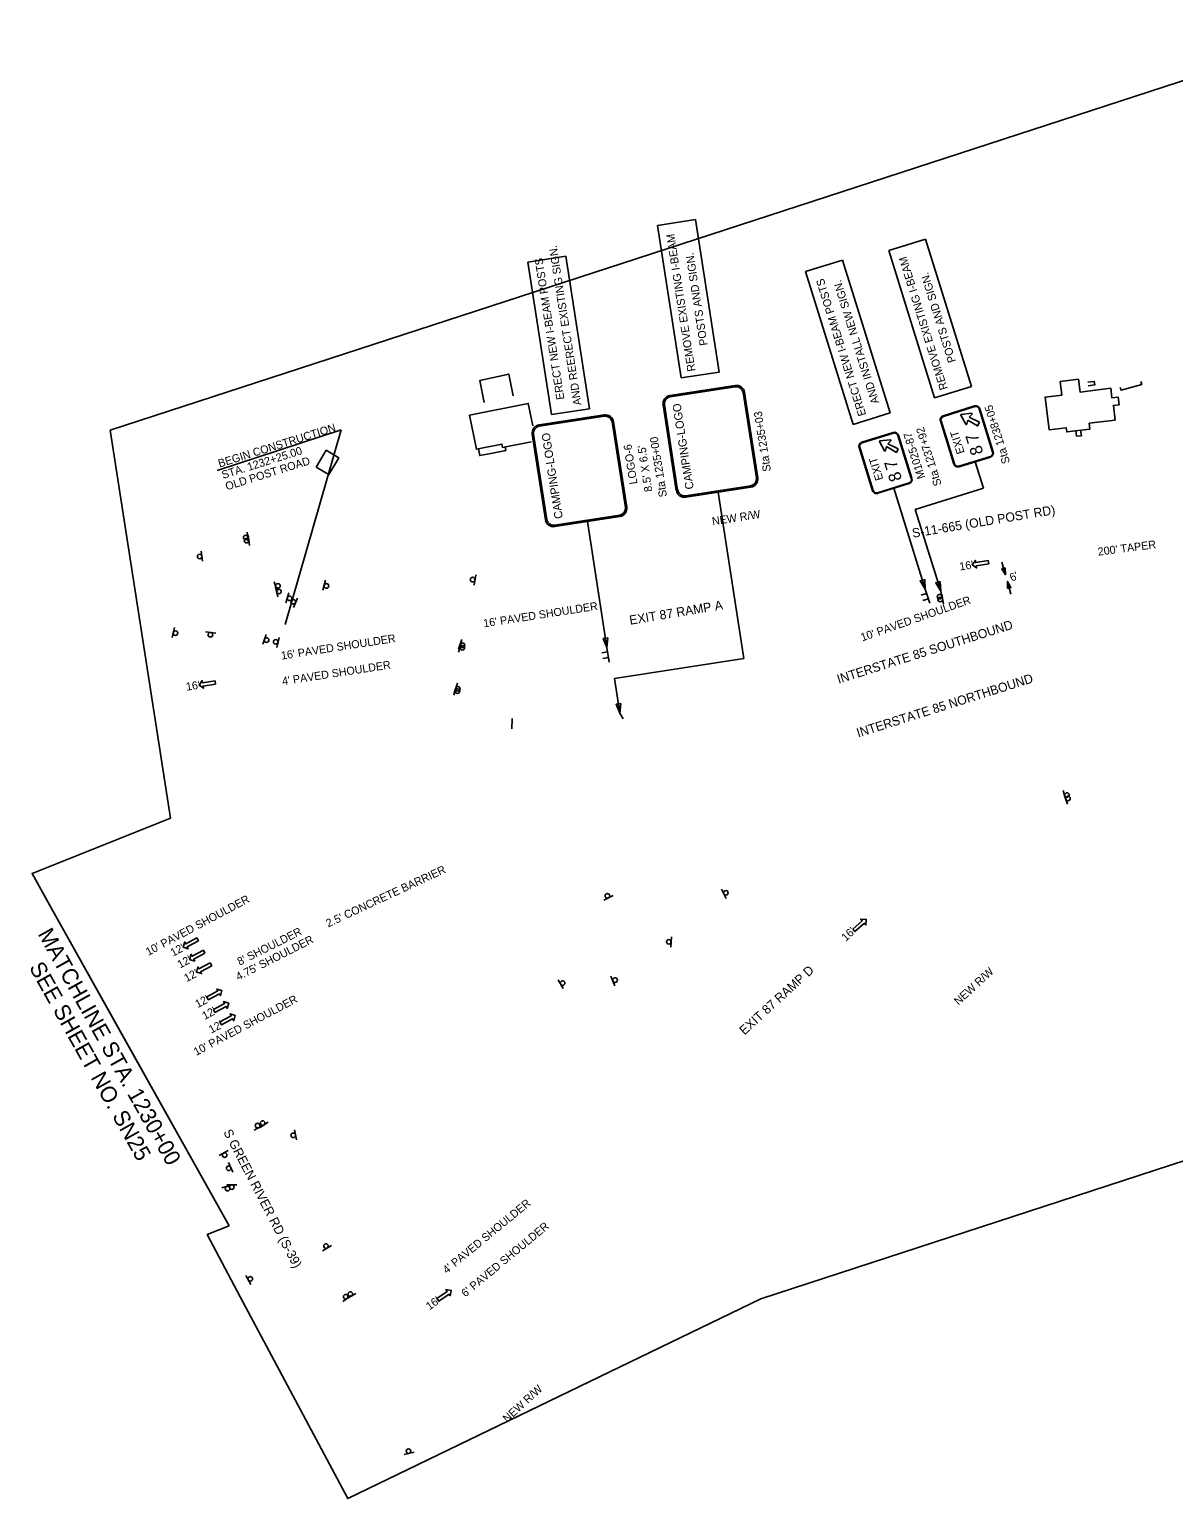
# Model space of a CAD drawing. Extents: x 1772383 to 1773934, y 1178785 to 1180160.
# Drawn here: x 1772383 to 1773384, y 1178785 to 1180070 of the extents above; entities that cross this region are included whole.
import ezdxf

# ---------------------------------------------------------------- set-up
doc = ezdxf.new("R2010")
doc.units = 0
for name, color, linetype in [('RD_EX_Bldg', 7, 'Continuous'), ('RD_EX_Conc', 7, 'Continuous'), ('RD_PD_Final_LnLine', 7, 'Continuous'), ('RD_PD_Final_TX', 7, 'Continuous'), ('RD_PD_RW_TX', 7, 'Continuous'), ('RD_SHT_MatchLine', 7, 'Continuous'), ('RD_SHT_ShtClip', 7, 'Continuous'), ('RD_TX_Drainage', 7, 'Continuous'), ('RD_TX_RoadID', 7, 'Continuous'), ('SN_P_Signs', 7, 'Continuous')]:
    doc.layers.add(name, color=color, linetype=linetype)

# ---------------------------------------------------------------- blocks, each defined once
blk = doc.blocks.new('SARRW2')
at = {"layer": 'RD_PD_Final_LnLine'}
blk.add_lwpolyline([(-12, 1.2), (-12, -1.2), (-2.8, -1.2), (-2.8, -2.8), (0, 0), (-2.8, 2.8), (-2.8, 1.2)], close=True, dxfattribs=at)
blk = doc.blocks.new('AH')
at = {"layer": 'RD_TX_Drainage'}
blk.add_lwpolyline([(-6, 1.5), (0, 0), (-6, -1.5)], close=True, dxfattribs=at)

msp = doc.modelspace()

# ---------------------------------------------------------------- linework, layer by layer
at = {"layer": 'RD_EX_Bldg'}
for points in [[(1773332.8, 1179728.1), (1773310, 1179725.3), (1773310.6, 1179720.2), (1773290.4, 1179717.7), (1773289.9, 1179721.4), (1773275, 1179719.6), (1773271.5, 1179748.1), (1773286.2, 1179749.9), (1773284.7, 1179761.9), (1773300.6, 1179763.8), (1773302, 1179752.6), (1773328.8, 1179755.9), (1773329.9, 1179747.4), (1773335.3, 1179748.1), (1773336.2, 1179741.5), (1773331.2, 1179740.9), (1773332.8, 1179728.1)], [(1772822, 1179709.1), (1772797.1, 1179704.1), (1772796.6, 1179707), (1772774.2, 1179702.5), (1772768.3, 1179732.4), (1772819.6, 1179742.6), (1772823.5, 1179722.9)], [(1772634.2, 1179687), (1772642.9, 1179701.6), (1772653.9, 1179695.1), (1772645.3, 1179680.5), (1772634.2, 1179687)]]:
    msp.add_lwpolyline(points, dxfattribs=at)
at = {"layer": 'RD_EX_Conc'}
msp.add_line((1773299, 1179714), (1773298.4, 1179718.7), dxfattribs=at)
for points in [[(1772781.1, 1179743.5), (1772777.3, 1179762.8), (1772802.5, 1179768.3), (1772806.5, 1179749.2)], [(1773309.2, 1179758), (1773314.9, 1179758.8), (1773314.5, 1179761.9), (1773308.9, 1179761.2)], [(1773337, 1179756.6), (1773337.9, 1179754.1), (1773356, 1179759.3), (1773355.2, 1179761.8)], [(1773302.3, 1179719.2), (1773303.2, 1179714.4), (1773299, 1179714)], [(1772776.1, 1179702.9), (1772777.2, 1179697), (1772786.9, 1179698.9), (1772800.1, 1179701.5), (1772799.5, 1179704.6)]]:
    msp.add_lwpolyline(points, dxfattribs=at)
at = {"layer": 'RD_PD_Final_TX'}
for p, q in [((1772547.5, 1179684), (1772656.1, 1179719.4)), ((1772606.9, 1179549.3), (1772656.1, 1179719.4)), ((1773236.9, 1179592.7), (1773233.6, 1179603.7)), ((1773238.5, 1179586.9), (1773241.6, 1179575.9))]:
    msp.add_line(p, q, dxfattribs=at)
at = {"layer": 'RD_SHT_MatchLine'}
msp.add_lwpolyline([(1772545.9, 1179045.1), (1772463.5, 1179192.4), (1772402.4, 1179301.5)], dxfattribs=at)
at = {"layer": 'RD_SHT_ShtClip'}
msp.add_lwpolyline([(1772558.1, 1179023.3), (1772538.9, 1179015.6), (1772567.8, 1178961.2), (1772661.7, 1178784.6), (1773022.9, 1178959.4), (1773601.8, 1179148.2), (1773904.9, 1179498.8), (1773856.3, 1179813.1), (1773835, 1179950.4), (1773829.6, 1179985.5), (1773529.5, 1180069.8), (1772454.1, 1179719.2), (1772506.7, 1179379.7), (1772385.8, 1179331.3), (1772402.4, 1179301.5), (1772545.9, 1179045.1)], close=True, dxfattribs=at)
at = {"layer": 'SN_P_Signs'}
for p, q in [((1772932.6, 1179898.3), (1772965.8, 1179903.4)), ((1772953.2, 1179764.9), (1772932.6, 1179898.3)), ((1772965.8, 1179903.4), (1772986.5, 1179770)), ((1773134.7, 1179876.4), (1773166.8, 1179886.4)), ((1773166.8, 1179886.4), (1773207, 1179757.5)), ((1772819.1, 1179866.3), (1772852.3, 1179871.4)), ((1772852.3, 1179871.4), (1772873, 1179738)), ((1773062.1, 1179858), (1773094.2, 1179868)), ((1773094.2, 1179868), (1773135.9, 1179734.3)), ((1773174.9, 1179747.5), (1773134.7, 1179876.4)), ((1772839.8, 1179732.9), (1772819.1, 1179866.3)), ((1773103.8, 1179724.3), (1773062.1, 1179858)), ((1772986.5, 1179770), (1772953.2, 1179764.9)), ((1773207, 1179757.5), (1773174.9, 1179747.5)), ((1773182.3, 1179731.8), (1773209.8, 1179740.4)), ((1773182.5, 1179731.3), (1773210, 1179739.8)), ((1772873, 1179738), (1772839.8, 1179732.9)), ((1773135.9, 1179734.3), (1773103.8, 1179724.3)), ((1773191.7, 1179689.5), (1773179.9, 1179727.3)), ((1773192.3, 1179689.7), (1773180.5, 1179727.5)), ((1773213.7, 1179737.9), (1773225.5, 1179700.1)), ((1773214.3, 1179738), (1773226.1, 1179700.2)), ((1773111.2, 1179708.7), (1773138.7, 1179717.2)), ((1773111.4, 1179708.1), (1773138.9, 1179716.7)), ((1773142.6, 1179714.7), (1773154.4, 1179676.9)), ((1773143.2, 1179714.9), (1773155, 1179677.1)), ((1773120.6, 1179666.3), (1773108.8, 1179704.1)), ((1773121.2, 1179666.5), (1773109.4, 1179704.3)), ((1773223.6, 1179696.3), (1773196.1, 1179687.7)), ((1773223.7, 1179695.7), (1773196.2, 1179687.2)), ((1773210.3, 1179691.5), (1773217.5, 1179668.5)), ((1772985.7, 1179665), (1773008.2, 1179519.4)), ((1773152.5, 1179673.1), (1773125, 1179664.5)), ((1773152.6, 1179672.6), (1773125.1, 1179664)), ((1773139.2, 1179668.4), (1773166.7, 1179580.2)), ((1773158, 1179649.9), (1773217.5, 1179668.5)), ((1773158, 1179649.9), (1773180.3, 1179578.3)), ((1772871.3, 1179639.3), (1772888.3, 1179529.1)), ((1772575.1, 1179621.1), (1772573.9, 1179630)), ((1772575.8, 1179618.4), (1772574.6, 1179627.3)), ((1772534.9, 1179604.5), (1772533.7, 1179613.4)), ((1772597.3, 1179586.7), (1772600.2, 1179578.2)), ((1772642.4, 1179588), (1772639.9, 1179579.3)), ((1772772.2, 1179583.7), (1772773.6, 1179592.6)), ((1772598.5, 1179582), (1772600.7, 1179573.3)), ((1772610.2, 1179577), (1772607.7, 1179568.3)), ((1772614.2, 1179564.1), (1772617.7, 1179572.4)), ((1773167.9, 1179576.5), (1773163.1, 1179575)), ((1773169.4, 1179571.7), (1773164.6, 1179570.2)), ((1773166.7, 1179580.2), (1773170.6, 1179567.8)), ((1773182.1, 1179569.5), (1773180.3, 1179578.3)), ((1773182.5, 1179567), (1773181.1, 1179575.9)), ((1772510.2, 1179546.6), (1772508.3, 1179537.8)), ((1772546.4, 1179541.8), (1772537.5, 1179542.9)), ((1772590.5, 1179540.5), (1772587.4, 1179532)), ((1772599.7, 1179529.2), (1772601.7, 1179538)), ((1772761.5, 1179536.1), (1772758.6, 1179527.6)), ((1772761.3, 1179533.7), (1772758.7, 1179525.1)), ((1772888.9, 1179525.3), (1772884, 1179524.5)), ((1772889.7, 1179520.3), (1772884.8, 1179519.5)), ((1772888.3, 1179529.1), (1772890.3, 1179516.2)), ((1773008.2, 1179519.4), (1772895, 1179501.9)), ((1772757.3, 1179495.8), (1772754.4, 1179487.3)), ((1772757.6, 1179497.9), (1772754.7, 1179489.4)), ((1772895, 1179501.9), (1772899.7, 1179471.7)), ((1772902.5, 1179466.7), (1772899.7, 1179471.7)), ((1772805.2, 1179458), (1772805.6, 1179467)), ((1773287.4, 1179403.9), (1773290, 1179395.3)), ((1773288, 1179400.6), (1773291.1, 1179392.2)), ((1772988.5, 1179317.7), (1772992.5, 1179309.6)), ((1772885.8, 1179308), (1772893.7, 1179312.2)), ((1772944.2, 1179267), (1772944.8, 1179276)), ((1772845.8, 1179238.5), (1772850.2, 1179230.7)), ((1772891.9, 1179241.6), (1772895.4, 1179233.3)), ((1772579.9, 1179107), (1772587.9, 1179111.2)), ((1772584.7, 1179109), (1772592.3, 1179113.8)), ((1772617, 1179098.5), (1772615.1, 1179107.2)), ((1772557.1, 1179089), (1772549.2, 1179084.8)), ((1772561.2, 1179070.3), (1772557.6, 1179078.6)), ((1772560.5, 1179059.1), (1772551.8, 1179056.5)), ((1772564.9, 1179059.1), (1772555.9, 1179059.1)), ((1772639.7, 1179001.5), (1772647.6, 1179005.9)), ((1772572.6, 1178979.9), (1772576.9, 1178972)), ((1772657.4, 1178956.9), (1772664.7, 1178962.3)), ((1772661.1, 1178959.6), (1772668.9, 1178964.1)), ((1772711, 1178823.1), (1772719.8, 1178825.1))]:
    msp.add_line(p, q, dxfattribs=at)
for points in [[(1772943.5, 1179749.5), (1773000.4, 1179758.3)], [(1772943.7, 1179748.3), (1773000.6, 1179757.2)], [(1773007.4, 1179752.1), (1773019, 1179677.4)], [(1773008.6, 1179752.3), (1773020.2, 1179677.6)], [(1772949, 1179666.6), (1772937.5, 1179741.3)], [(1772950.2, 1179666.8), (1772938.7, 1179741.5)], [(1772829.1, 1179723.8), (1772886, 1179732.6)], [(1772829.2, 1179722.6), (1772886.2, 1179731.4)], [(1772893, 1179726.4), (1772904.6, 1179651.7)], [(1772894.2, 1179726.6), (1772905.8, 1179651.9)], [(1773202.2, 1179724.4), (1773197.8, 1179732.4)], [(1773198.2, 1179733), (1773207.2, 1179734)], [(1773203.9, 1179728.1), (1773203, 1179724.5)], [(1773214.2, 1179726.2), (1773212.5, 1179723), (1773203.9, 1179728.1)], [(1773207.6, 1179733.2), (1773205.1, 1179730.5)], [(1773205.1, 1179730.5), (1773214.2, 1179726.2)], [(1772834.6, 1179640.9), (1772823, 1179715.6)], [(1772835.8, 1179641.1), (1772824.2, 1179715.8)], [(1773131.1, 1179701.2), (1773126.8, 1179709.2)], [(1773127.1, 1179709.8), (1773136.1, 1179710.8)], [(1773132.8, 1179704.9), (1773131.9, 1179701.3)], [(1773143.1, 1179703), (1773141.5, 1179699.8), (1773132.8, 1179704.9)], [(1773136.5, 1179710), (1773134, 1179707.3)], [(1773134, 1179707.3), (1773143.1, 1179703)], [(1773014, 1179670.6), (1772957.1, 1179661.8)], [(1773014.2, 1179669.4), (1772957.3, 1179660.6)], [(1772899.6, 1179644.9), (1772842.6, 1179636)], [(1772899.7, 1179643.7), (1772842.8, 1179634.9)]]:
    msp.add_lwpolyline(points, dxfattribs=at)
for points in [[(1773166.2, 1179588.7), (1773166.7, 1179580.2), (1773162.3, 1179587.5)], [(1773179.8, 1179586.8), (1773180.3, 1179578.3), (1773175.9, 1179585.6)], [(1772889.1, 1179537.5), (1772888.3, 1179529.1), (1772885.1, 1179536.9)], [(1772900.4, 1179480.2), (1772899.7, 1179471.7), (1772896.4, 1179479.5)]]:
    msp.add_lwpolyline(points, close=True, dxfattribs=at)
for centre in [(1772572.5, 1179625.3), (1772573.2, 1179622.6), (1772532.3, 1179608.7), (1772600.7, 1179583.1), (1772643.1, 1179583), (1772770.9, 1179588.5), (1772601.6, 1179578.1), (1772610.9, 1179572.1), (1773179.2, 1179573.6), (1773179.8, 1179571.1), (1772614.1, 1179569.1), (1772511.2, 1179541.7), (1772541.7, 1179540.3), (1772590.8, 1179535.6), (1772598.8, 1179534.1), (1772762, 1179531.1), (1772761.9, 1179528.8), (1772758, 1179493), (1772757.7, 1179490.9), (1773290.6, 1179400.1), (1773291.5, 1179397.1), (1772992.3, 1179314.5), (1772888.8, 1179311.9), (1772942.5, 1179271.7), (1772849.7, 1179235.6), (1772895.5, 1179238.2), (1772582.9, 1179110.9), (1772587.4, 1179113.1), (1772614.1, 1179102.4), (1772554.1, 1179085.1), (1772557.6, 1179073.6), (1772556.7, 1179055.8), (1772560.4, 1179057.1), (1772642.7, 1179005.5), (1772576.6, 1178976.9), (1772659.9, 1178961.2), (1772664, 1178963.6), (1772714.9, 1178826.1)]:
    msp.add_circle(centre, 2, dxfattribs=at)
for centre, radius, start, end in [((1773001.5, 1179751.2), 7.2, 8.8, 98.8), ((1773001.5, 1179751.2), 6, 8.8, 98.8), ((1772944.6, 1179742.4), 7.2, 98.8, 188.8), ((1772944.6, 1179742.4), 6, 98.8, 188.8), ((1773210.9, 1179737), 3.6, 17.3283, 107.3283), ((1773210.9, 1179737), 3, 17.3283, 107.3283), ((1772887.1, 1179725.5), 7.2, 8.8, 98.8), ((1772887.1, 1179725.5), 6, 8.8, 98.8), ((1773183.4, 1179728.4), 3.6, 107.3283, 197.3283), ((1773183.4, 1179728.4), 3, 107.3283, 197.3283), ((1773198.2, 1179732.6), 0.45, 96.1504, 208.5062), ((1773207.2, 1179733.5), 0.45, 318.3662, 96.1504), ((1772830.2, 1179716.7), 7.2, 98.8, 188.8), ((1772830.2, 1179716.7), 6, 98.8, 188.8), ((1773139.8, 1179713.8), 3.6, 17.3283, 107.3283), ((1773139.8, 1179713.8), 3, 17.3283, 107.3283), ((1773202.5, 1179724.6), 0.45, 208.5062, 346.2904), ((1773112.3, 1179705.2), 3.6, 107.3283, 197.3283), ((1773112.3, 1179705.2), 3, 107.3283, 197.3283), ((1773127.1, 1179709.4), 0.45, 96.1504, 208.5062), ((1773131.5, 1179701.4), 0.45, 208.5062, 346.2904), ((1773136.1, 1179710.3), 0.45, 318.3662, 96.1504), ((1773222.7, 1179699.2), 3, 287.3283, 17.3283), ((1773222.7, 1179699.2), 3.6, 287.3283, 17.3283), ((1773195.2, 1179690.6), 3.6, 197.3283, 287.3283), ((1773195.2, 1179690.6), 3, 197.3283, 287.3283), ((1773013.1, 1179676.5), 6, 278.8, 8.8), ((1773013.1, 1179676.5), 7.2, 278.8, 8.8), ((1773151.6, 1179676), 3, 287.3283, 17.3283), ((1773151.6, 1179676), 3.6, 287.3283, 17.3283), ((1772956.2, 1179667.7), 7.2, 188.8, 278.8), ((1772956.2, 1179667.7), 6, 188.8, 278.8), ((1773124.1, 1179667.4), 3.6, 197.3283, 287.3283), ((1773124.1, 1179667.4), 3, 197.3283, 287.3283), ((1772898.6, 1179650.8), 6, 278.8, 8.8), ((1772898.6, 1179650.8), 7.2, 278.8, 8.8), ((1772841.7, 1179642), 7.2, 188.8, 278.8), ((1772841.7, 1179642), 6, 188.8, 278.8)]:
    msp.add_arc(centre, radius, start, end, dxfattribs=at)

# ---------------------------------------------------------------- block references
at = {"layer": 'RD_PD_Final_LnLine'}
for p, xscale, yscale, rotation in [((1773207.8, 1179601.5), 1.2, 1.2, -171.19998882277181), ((1772531.7, 1179496.3), 1.2, 1.2, -171.19998882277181), ((1773115.1, 1179291.2), 1.1999999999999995, 1.2000000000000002, 41.435473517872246), ((1773115.1, 1179291.2), 1.1999999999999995, 1.2000000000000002, 41.435473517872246), ((1772517.8, 1179267), 1.2, 1.2000000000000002, -151.9473681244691), ((1772523.5, 1179256.2), 1.2, 1.2000000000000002, -151.9473681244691), ((1772529.4, 1179245.2), 1.2, 1.2000000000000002, -151.9473681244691), ((1772551.8, 1179229), 1.1999999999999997, 1.2000000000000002, 28.052631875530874), ((1772557.7, 1179218), 1.1999999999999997, 1.2000000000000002, 28.052631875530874), ((1772563.4, 1179207.2), 1.1999999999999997, 1.2000000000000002, 28.052631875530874), ((1772752.2, 1178966.7), 1.1999999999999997, 1.1999999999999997, 35.391952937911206)]:
    msp.add_blockref('SARRW2', p, dxfattribs=dict(at, xscale=xscale, yscale=yscale, rotation=rotation))
at = {"layer": 'RD_PD_Final_TX'}
for p, rotation in [((1773236.9, 1179592.7), -73.7125457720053), ((1773238.5, 1179586.9), 105.5366000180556)]:
    msp.add_blockref('AH', p, dxfattribs=dict(at, rotation=rotation))

# ---------------------------------------------------------------- texts
for s, rotation, p in [('BEGIN CONSTRUCTION', 17.4349, (1772549.7, 1179686.5)), ('STA. 1232+25.00', 17.4349, (1772552.8, 1179676.5)), ('OLD POST ROAD', 17.4349, (1772556, 1179666.5)), ("200' TAPER", 7.451, (1773318, 1179609.4)), ("16'", 8.8, (1773197.1, 1179596.4)), ("6'", 25.6513, (1773242.5, 1179586.6)), ("10' PAVED SHOULDER", 19.3188, (1773111.7, 1179534.4)), ("16' PAVED SHOULDER", 8.8, (1772780.8, 1179546.7)), ("16' PAVED SHOULDER", 8.8, (1772604, 1179518.5)), ("4' PAVED SHOULDER", 8.8, (1772604.9, 1179496.1)), ("16'", 8.8, (1772520.9, 1179491.3)), ("2.5' CONCRETE BARRIER", 25.0227, (1772644.7, 1179284.2)), ("10' PAVED SHOULDER", 28.0526, (1772487.4, 1179259.3)), ("8' SHOULDER", 26.7751, (1772567.3, 1179250.7)), ("4.75' SHOULDER", 27.0075, (1772566.1, 1179237.6)), ("16'", 42.9091, (1773097.3, 1179271.7)), ("16'", 42.9091, (1773097.3, 1179271.7)), ("12'", 28.0526, (1772509, 1179258.6)), ("12'", 28.0526, (1772515.1, 1179248.2)), ("12'", 28.0526, (1772520.9, 1179236.3)), ("10' PAVED SHOULDER", 28.0526, (1772529.3, 1179171.8)), ("12'", 28.0526, (1772530.6, 1179213.6)), ("12'", 28.0526, (1772536.7, 1179203.3)), ("12'", 28.0526, (1772542.5, 1179191.3)), ("4' PAVED SHOULDER", 39.486, (1772748.3, 1178980.9)), ("6' PAVED SHOULDER", 39.7235, (1772764.6, 1178960.5)), ("16'", 35.392, (1772733.2, 1178949.2))]:
    msp.add_text(s, height=7, rotation=rotation, dxfattribs=at).set_placement(p)
at = {"layer": 'RD_PD_RW_TX'}
for rotation, p in [(8.8, (1772980.8, 1179636)), (42.5494, (1773195.7, 1179215.9)), (42.5494, (1772801.2, 1178850.8))]:
    msp.add_text('NEW R/W', height=7, rotation=rotation, dxfattribs=at).set_placement(p)
at = {"layer": 'RD_SHT_MatchLine'}
for s, p in [('MATCHLINE STA. 1230+00', (1772390.4, 1179278.6)), ('SEE SHEET NO. SN25', (1772382.8, 1179249.3))]:
    msp.add_text(s, height=14, rotation=299.216, dxfattribs=at).set_placement(p)
at = {"layer": 'RD_TX_RoadID'}
for s, rotation, p in [('S-11-665 (OLD POST RD)', 9.4323, (1773155.9, 1179625.1)), ('EXIT 87 RAMP A', 9.4323, (1772908.7, 1179549)), ('INTERSTATE 85 SOUTHBOUND', 17.5265, (1773091, 1179497.4)), ('INTERSTATE 85 NORTHBOUND', 17.4868, (1773108.1, 1179450.4)), ('EXIT 87 RAMP D', 42.3902, (1773008.6, 1179189.7)), ('EXIT 87 RAMP D', 42.3902, (1773008.6, 1179189.7)), ('S GREEN RIVER RD (S-39)', 297.3816, (1772552.8, 1179105.2))]:
    msp.add_text(s, height=8, rotation=rotation, dxfattribs=at).set_placement(p)
at = {"layer": 'SN_P_Signs'}
for s, height, rotation, p in [('AND REERECT EXISTING SIGN.', 7, 98.8001, (1772866.1, 1179741.5)), ('REMOVE EXISTING I-BEAM', 7, 98.8001, (1772965.8, 1179771.1)), ('ERECT NEW I-BEAM POSTS', 7, 98.8001, (1772851.2, 1179746.4)), ('POSTS AND SIGN.', 7, 98.8001, (1772976.5, 1179793.7)), ('REMOVE EXISTING I-BEAM', 7, 107.3284, (1773186.4, 1179755.6)), ('POSTS AND SIGN.', 7, 107.3284, (1773193.6, 1179779.5)), ('ERECT NEW I-BEAM POSTS', 7, 107.3284, (1773115.1, 1179732.8)), ('AND INSTALL NEW SIGN.', 7, 107.3284, (1773126.5, 1179743.4)), ('CAMPING-LOGO', 7.2, 98.8, (1772964.3, 1179668)), ('Sta 1238+05', 7, 107.3284, (1773240.9, 1179691)), ('Sta 1235+03', 7, 98.8001, (1773031.8, 1179683.5)), ('CAMPING-LOGO', 7.2, 98.8, (1772849.9, 1179642.3)), ('Sta 1235+00', 7, 98.8001, (1772940.9, 1179661.2)), ('M1025-87', 7, 107.3284, (1773166.7, 1179677.8)), ('Sta 1237+92', 7, 107.3284, (1773181.1, 1179671.6)), ('EXIT', 7, 107.3283, (1773201.2, 1179699.6)), ('7', 10.8, 107.3283, (1773214.3, 1179709.8)), ('LOGO-6', 7, 98.8001, (1772915.1, 1179672.4)), ("8.5' X 6.5'", 7, 98.8001, (1772928.2, 1179665.8)), ('8', 10.8, 107.3283, (1773217.6, 1179699.3)), ('EXIT', 7, 107.3283, (1773130.1, 1179676.4)), ('7', 10.8, 107.3283, (1773143.2, 1179686.6)), ('8', 10.8, 107.3283, (1773146.5, 1179676.2))]:
    msp.add_text(s, height=height, rotation=rotation, dxfattribs=at).set_placement(p)

doc.saveas('drawing.dxf')
